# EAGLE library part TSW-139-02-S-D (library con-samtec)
THROUGH-HOLE .025" SQ POST HEADER Source: Samtec TSW.pdf
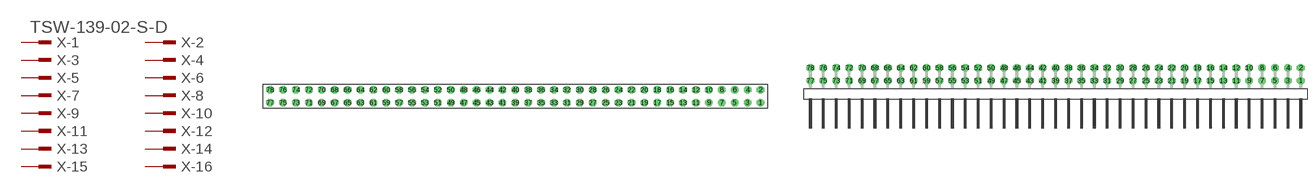
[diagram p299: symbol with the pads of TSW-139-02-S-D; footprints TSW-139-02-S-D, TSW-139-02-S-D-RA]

Designator prefix X; gates -1=MPINV -2=MPIN -3=MPIN -4=MPIN -5=MPIN -6=MPIN -7=MPIN -8=MPIN -9=MPIN -10=MPIN -11=MPIN -12=MPIN -13=MPIN -14=MPIN -15=MPIN -16=MPIN -17=MPIN -18=MPIN -19=MPIN -20=MPIN -21=MPIN -22=MPIN -23=MPIN -24=MPIN -25=MPIN -26=MPIN -27=MPIN -28=MPIN -29=MPIN -30=MPIN -31=MPIN -32=MPIN -33=MPIN -34=MPIN -35=MPIN -36=MPIN -37=MPIN -38=MPIN -39=MPIN -40=MPIN -41=MPIN -42=MPIN -43=MPIN -44=MPIN -45=MPIN -46=MPIN -47=MPIN -48=MPIN -49=MPIN -50=MPIN -51=MPIN -52=MPIN -53=MPIN -54=MPIN -55=MPIN -56=MPIN -57=MPIN -58=MPIN -59=MPIN -60=MPIN -61=MPIN -62=MPIN -63=MPIN -64=MPIN -65=MPIN -66=MPIN -67=MPIN -68=MPIN -69=MPIN -70=MPIN -71=MPIN -72=MPIN -73=MPIN -74=MPIN -75=MPIN -76=MPIN -77=MPIN -78=MPIN

## TSW-139-02-S-D (OC_FARNELL: unknown; OC_NEWARK: unknown)  [TSW-139-02-S-D]
1  -1:1  pas
2  -2:1  pas
3  -3:1  pas
4  -4:1  pas
5  -5:1  pas
6  -6:1  pas
7  -7:1  pas
8  -8:1  pas
9  -9:1  pas
10  -10:1  pas
11  -11:1  pas
12  -12:1  pas
13  -13:1  pas
14  -14:1  pas
15  -15:1  pas
16  -16:1  pas
17  -17:1  pas
18  -18:1  pas
19  -19:1  pas
20  -20:1  pas
21  -21:1  pas
22  -22:1  pas
23  -23:1  pas
24  -24:1  pas
25  -25:1  pas
26  -26:1  pas
27  -27:1  pas
28  -28:1  pas
29  -29:1  pas
30  -30:1  pas
31  -31:1  pas
32  -32:1  pas
33  -33:1  pas
34  -34:1  pas
35  -35:1  pas
36  -36:1  pas
37  -37:1  pas
38  -38:1  pas
39  -39:1  pas
40  -40:1  pas
41  -41:1  pas
42  -42:1  pas
43  -43:1  pas
44  -44:1  pas
45  -45:1  pas
46  -46:1  pas
47  -47:1  pas
48  -48:1  pas
49  -49:1  pas
50  -50:1  pas
51  -51:1  pas
52  -52:1  pas
53  -53:1  pas
54  -54:1  pas
55  -55:1  pas
56  -56:1  pas
57  -57:1  pas
58  -58:1  pas
59  -59:1  pas
60  -60:1  pas
61  -61:1  pas
62  -62:1  pas
63  -63:1  pas
64  -64:1  pas
65  -65:1  pas
66  -66:1  pas
67  -67:1  pas
68  -68:1  pas
69  -69:1  pas
70  -70:1  pas
71  -71:1  pas
72  -72:1  pas
73  -73:1  pas
74  -74:1  pas
75  -75:1  pas
76  -76:1  pas
77  -77:1  pas
78  -78:1  pas

## TSW-139-02-S-D-RA (OC_FARNELL: unknown; OC_NEWARK: unknown)  [TSW-139-02-S-D-RA]
Pads as for TSW-139-02-S-D

## Footprint TSW-139-02-S-D (pad centres in mm)
THROUGH-HOLE .025" SQ POST HEADER Source: Samtec TSW.pdf
drill 1 pad 1.5 octagon: 1 48.26,-1.27; 2 48.26,1.27; 3 45.72,-1.27; 4 45.72,1.27; 5 43.18,-1.27; 6 43.18,1.27; 7 40.64,-1.27; 8 40.64,1.27; 9 38.1,-1.27; 10 38.1,1.27; 11 35.56,-1.27; 12 35.56,1.27; 13 33.02,-1.27; 14 33.02,1.27; 15 30.48,-1.27; 16 30.48,1.27; 17 27.94,-1.27; 18 27.94,1.27; 19 25.4,-1.27; 20 25.4,1.27; 21 22.86,-1.27; 22 22.86,1.27; 23 20.32,-1.27; 24 20.32,1.27; 25 17.78,-1.27; 26 17.78,1.27; 27 15.24,-1.27; 28 15.24,1.27; 29 12.7,-1.27; 30 12.7,1.27; 31 10.16,-1.27; 32 10.16,1.27; 33 7.62,-1.27; 34 7.62,1.27; 35 5.08,-1.27; 36 5.08,1.27; 37 2.54,-1.27; 38 2.54,1.27; 39 0,-1.27; 40 0,1.27; 41 -2.54,-1.27; 42 -2.54,1.27; 43 -5.08,-1.27; 44 -5.08,1.27; 45 -7.62,-1.27; 46 -7.62,1.27; 47 -10.16,-1.27; 48 -10.16,1.27; 49 -12.7,-1.27; 50 -12.7,1.27; 51 -15.24,-1.27; 52 -15.24,1.27; 53 -17.78,-1.27; 54 -17.78,1.27; 55 -20.32,-1.27; 56 -20.32,1.27; 57 -22.86,-1.27; 58 -22.86,1.27; 59 -25.4,-1.27; 60 -25.4,1.27; 61 -27.94,-1.27; 62 -27.94,1.27; 63 -30.48,-1.27; 64 -30.48,1.27; 65 -33.02,-1.27; 66 -33.02,1.27; 67 -35.56,-1.27; 68 -35.56,1.27; 69 -38.1,-1.27; 70 -38.1,1.27; 71 -40.64,-1.27; 72 -40.64,1.27; 73 -43.18,-1.27; 74 -43.18,1.27; 75 -45.72,-1.27; 76 -45.72,1.27; 77 -48.26,-1.27; 78 -48.26,1.27

## Footprint TSW-139-02-S-D-RA (pad centres in mm)
THROUGH-HOLE .025" SQ POST HEADER Source: Samtec TSW.pdf
drill 1 pad 1.5 octagon: 1 48.26,1.524; 2 48.26,4.064; 3 45.72,1.524; 4 45.72,4.064; 5 43.18,1.524; 6 43.18,4.064; 7 40.64,1.524; 8 40.64,4.064; 9 38.1,1.524; 10 38.1,4.064; 11 35.56,1.524; 12 35.56,4.064; 13 33.02,1.524; 14 33.02,4.064; 15 30.48,1.524; 16 30.48,4.064; 17 27.94,1.524; 18 27.94,4.064; 19 25.4,1.524; 20 25.4,4.064; 21 22.86,1.524; 22 22.86,4.064; 23 20.32,1.524; 24 20.32,4.064; 25 17.78,1.524; 26 17.78,4.064; 27 15.24,1.524; 28 15.24,4.064; 29 12.7,1.524; 30 12.7,4.064; 31 10.16,1.524; 32 10.16,4.064; 33 7.62,1.524; 34 7.62,4.064; 35 5.08,1.524; 36 5.08,4.064; 37 2.54,1.524; 38 2.54,4.064; 39 0,1.524; 40 0,4.064; 41 -2.54,1.524; 42 -2.54,4.064; 43 -5.08,1.524; 44 -5.08,4.064; 45 -7.62,1.524; 46 -7.62,4.064; 47 -10.16,1.524; 48 -10.16,4.064; 49 -12.7,1.524; 50 -12.7,4.064; 51 -15.24,1.524; 52 -15.24,4.064; 53 -17.78,1.524; 54 -17.78,4.064; 55 -20.32,1.524; 56 -20.32,4.064; 57 -22.86,1.524; 58 -22.86,4.064; 59 -25.4,1.524; 60 -25.4,4.064; 61 -27.94,1.524; 62 -27.94,4.064; 63 -30.48,1.524; 64 -30.48,4.064; 65 -33.02,1.524; 66 -33.02,4.064; 67 -35.56,1.524; 68 -35.56,4.064; 69 -38.1,1.524; 70 -38.1,4.064; 71 -40.64,1.524; 72 -40.64,4.064; 73 -43.18,1.524; 74 -43.18,4.064; 75 -45.72,1.524; 76 -45.72,4.064; 77 -48.26,1.524; 78 -48.26,4.064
